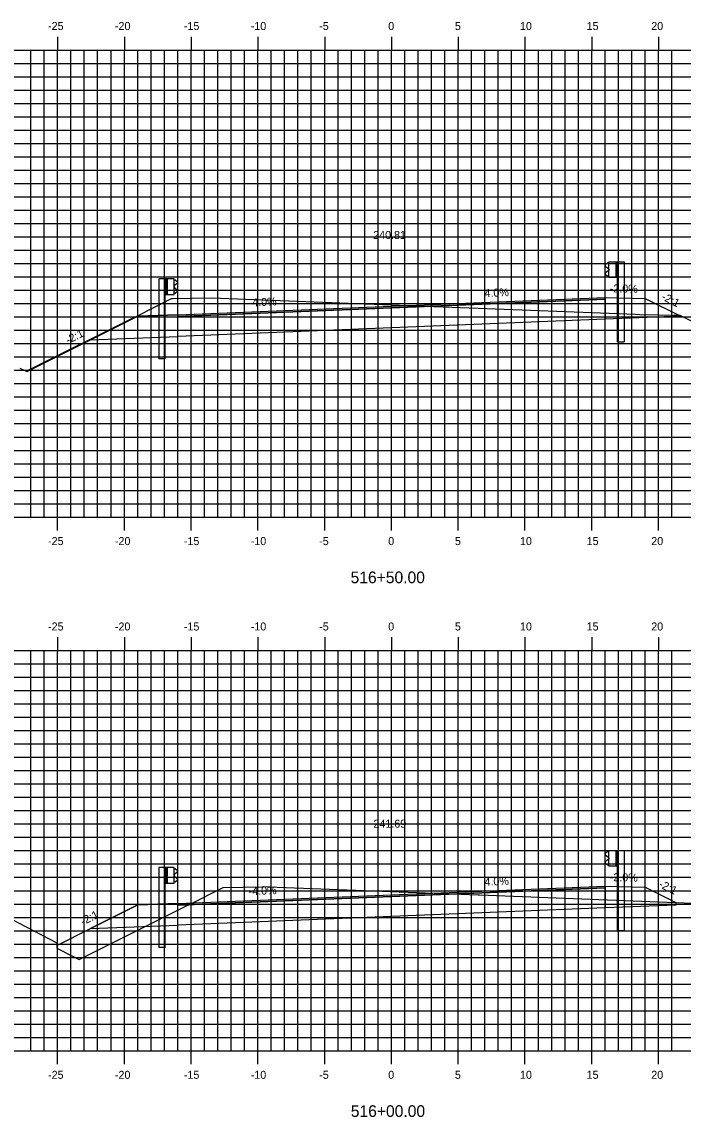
# Model space of a CAD drawing. Extents: x 1170543 to 1177585, y 609599 to 610623.
# Drawn here: x 1173703.4 to 1173752.9, y 610272.8 to 610354.9 of the extents above; entities that cross this region are included whole.
import ezdxf

# ---------------------------------------------------------------- set-up
doc = ezdxf.new("R2010")
doc.units = 0
for name, color, linetype in [('ANNOTATION', 7, 'Continuous'), ('D_Guardrail_Beam_Lt', 7, 'Continuous'), ('D_Guardrail_Beam_Rt', 7, 'Continuous'), ('D_Roadway_Centerline', 7, 'Continuous'), ('D_Roadway_Centerline_Text', 7, 'Continuous'), ('D_Roadway_Edge_Shoulder', 7, 'Continuous'), ('D_Roadway_Edge_TW', 7, 'Continuous'), ('D_Roadway_Pavement', 7, 'Continuous'), ('D_Roadway_SubGrade', 7, 'Continuous'), ('H_V ANNOTATION', 7, 'Continuous'), ('MAJOR', 7, 'Continuous'), ('MINOR', 7, 'Continuous'), ('S_Roadway_Centerline', 7, 'Continuous')]:
    doc.layers.add(name, color=color, linetype=linetype)

msp = doc.modelspace()

# ---------------------------------------------------------------- linework, layer by layer
at = {"layer": 'D_Guardrail_Beam_Lt'}
for p, q in [((1173713.634, 610335.654), (1173713.634, 610329.654)), ((1173714.104, 610335.654), (1173713.634, 610335.654)), ((1173714.792, 610335.654), (1173714.104, 610335.654)), ((1173714.104, 610335.654), (1173714.104, 610334.487)), ((1173714.167, 610335.654), (1173714.167, 610334.487)), ((1173714.271, 610335.654), (1173714.271, 610334.487)), ((1173714.792, 610334.487), (1173714.792, 610335.654)), ((1173714.792, 610335.571), (1173714.866, 610335.556)), ((1173714.882, 610335.549), (1173715.025, 610335.449)), ((1173714.866, 610334.585), (1173714.792, 610334.571)), ((1173714.796, 610335.106), (1173714.796, 610335.036)), ((1173715.025, 610335.306), (1173714.83, 610335.17)), ((1173714.83, 610334.971), (1173715.025, 610334.835)), ((1173715.025, 610334.692), (1173714.882, 610334.592)), ((1173714.104, 610334.487), (1173714.792, 610334.487)), ((1173714.125, 610329.654), (1173714.125, 610334.487)), ((1173714.125, 610329.654), (1173713.634, 610329.654)), ((1173713.634, 610291.533), (1173713.634, 610285.533)), ((1173714.104, 610291.533), (1173713.634, 610291.533)), ((1173714.792, 610291.533), (1173714.104, 610291.533)), ((1173714.104, 610291.533), (1173714.104, 610290.367)), ((1173714.167, 610291.533), (1173714.167, 610290.367)), ((1173714.271, 610291.533), (1173714.271, 610290.367)), ((1173714.792, 610290.367), (1173714.792, 610291.533)), ((1173714.792, 610291.45), (1173714.866, 610291.435)), ((1173715.025, 610291.186), (1173714.83, 610291.049)), ((1173714.882, 610291.429), (1173715.025, 610291.329)), ((1173714.104, 610290.367), (1173714.792, 610290.367)), ((1173714.125, 610285.533), (1173714.125, 610290.367)), ((1173714.866, 610290.465), (1173714.792, 610290.45)), ((1173714.796, 610290.985), (1173714.796, 610290.915)), ((1173714.83, 610290.851), (1173715.025, 610290.714)), ((1173715.025, 610290.571), (1173714.882, 610290.471)), ((1173714.125, 610285.533), (1173713.634, 610285.533))]:
    msp.add_line(p, q, dxfattribs=at)
for centre, major_axis, start_param, end_param in [((1173714.858, 610335.515), (0.0417, 0), 0.959931, 1.376053), ((1173714.975, 610335.378), (0.0877, 0), 5.323254, 7.243116), ((1173714.875, 610335.106), (-0.0789, 0), 5.323254, 6.283185), ((1173714.875, 610335.036), (-0.0789, 0), 6.283185, 7.243116), ((1173714.858, 610334.626), (0.0417, 0), 4.907132, 5.323254), ((1173714.975, 610334.764), (0.0877, 0), 5.323254, 7.243116), ((1173714.858, 610291.395), (0.0417, 0), 0.959931, 1.376053), ((1173714.975, 610291.257), (0.0877, 0), 5.323254, 7.243116), ((1173714.875, 610290.985), (-0.0789, 0), 5.323254, 6.283185), ((1173714.875, 610290.915), (-0.0789, 0), 6.283185, 7.243116), ((1173714.858, 610290.505), (0.0417, 0), 4.907132, 5.323254), ((1173714.975, 610290.643), (0.0877, 0), 5.323254, 7.243116)]:
    msp.add_ellipse(centre, major_axis=major_axis, ratio=0.995501, start_param=start_param, end_param=end_param, dxfattribs=at)
at = {"layer": 'D_Guardrail_Beam_Rt'}
for p, q in [((1173747.244, 610336.829), (1173747.1, 610336.729)), ((1173747.1, 610336.586), (1173747.296, 610336.45)), ((1173747.296, 610336.251), (1173747.1, 610336.115)), ((1173747.334, 610336.851), (1173747.26, 610336.836)), ((1173747.329, 610336.386), (1173747.329, 610336.316)), ((1173747.334, 610336.934), (1173748.021, 610336.934)), ((1173747.334, 610335.767), (1173747.334, 610336.934)), ((1173747.854, 610336.934), (1173747.854, 610335.767)), ((1173747.959, 610336.934), (1173747.959, 610335.767)), ((1173748.021, 610336.934), (1173748.492, 610336.934)), ((1173748.021, 610336.934), (1173748.021, 610335.767)), ((1173748.492, 610336.934), (1173748.492, 610330.934)), ((1173747.1, 610335.972), (1173747.244, 610335.872)), ((1173747.26, 610335.865), (1173747.334, 610335.851)), ((1173748.021, 610335.767), (1173747.334, 610335.767)), ((1173748, 610330.934), (1173748, 610335.767)), ((1173748, 610330.934), (1173748.492, 610330.934)), ((1173747.244, 610292.709), (1173747.1, 610292.609)), ((1173747.334, 610292.73), (1173747.26, 610292.715)), ((1173747.334, 610292.813), (1173748.021, 610292.813)), ((1173747.334, 610291.647), (1173747.334, 610292.813)), ((1173747.854, 610292.813), (1173747.854, 610291.647)), ((1173747.959, 610292.813), (1173747.959, 610291.647)), ((1173748.021, 610292.813), (1173748.492, 610292.813)), ((1173748.021, 610292.813), (1173748.021, 610291.647)), ((1173748.492, 610292.813), (1173748.492, 610286.813)), ((1173747.1, 610292.466), (1173747.296, 610292.329)), ((1173747.296, 610292.131), (1173747.1, 610291.994)), ((1173747.329, 610292.265), (1173747.329, 610292.195)), ((1173747.1, 610291.851), (1173747.244, 610291.751)), ((1173747.26, 610291.745), (1173747.334, 610291.73)), ((1173748.021, 610291.647), (1173747.334, 610291.647)), ((1173748, 610286.813), (1173748, 610291.647)), ((1173748, 610286.813), (1173748.492, 610286.813))]:
    msp.add_line(p, q, dxfattribs=at)
for centre, major_axis, start_param, end_param in [((1173747.151, 610336.658), (-0.0877, 0), 5.323254, 7.243116), ((1173747.268, 610336.795), (-0.0417, 0), 4.907132, 5.323254), ((1173747.25, 610336.386), (0.0789, 0), 0, 0.959931), ((1173747.25, 610336.316), (0.0789, 0), 5.323254, 6.283185), ((1173747.151, 610336.044), (-0.0877, 0), 5.323254, 7.243116), ((1173747.268, 610335.906), (-0.0417, 0), 0.959931, 1.376053), ((1173747.268, 610292.675), (-0.0417, 0), 4.907132, 5.323254), ((1173747.151, 610292.537), (-0.0877, 0), 5.323254, 7.243116), ((1173747.151, 610291.923), (-0.0877, 0), 5.323254, 7.243116), ((1173747.25, 610292.265), (0.0789, 0), 0, 0.959931), ((1173747.25, 610292.195), (0.0789, 0), 5.323254, 6.283185), ((1173747.268, 610291.785), (-0.0417, 0), 0.959931, 1.376053)]:
    msp.add_ellipse(centre, major_axis=major_axis, ratio=0.995501, start_param=start_param, end_param=end_param, dxfattribs=at)
at = {"layer": 'D_Roadway_Centerline'}
for points in [[(1173703.72, 610328.731), (1173703.774, 610328.704), (1173712.063, 610332.848), (1173715.063, 610332.968), (1173731.063, 610333.608), (1173747.063, 610334.248), (1173750.063, 610334.188), (1173752.739, 610332.85)], [(1173706, 610285.696), (1173708.53, 610286.961), (1173712.063, 610288.728), (1173715.063, 610288.848), (1173731.063, 610289.488), (1173747.063, 610290.128), (1173750.063, 610290.068), (1173752.352, 610288.923)]]:
    msp.add_lwpolyline(points, dxfattribs=at)
at = {"layer": 'D_Roadway_Edge_Shoulder'}
for points in [[(1173747.063, 610334.248), (1173747.063, 610334.123)], [(1173715.063, 610332.968), (1173715.063, 610332.843)], [(1173747.063, 610290.128), (1173747.063, 610290.003)], [(1173715.063, 610288.848), (1173715.063, 610288.723)]]:
    msp.add_lwpolyline(points, dxfattribs=at)
at = {"layer": 'D_Roadway_Edge_TW'}
for points in [[(1173715.063, 610332.843), (1173715.063, 610332.968), (1173731.063, 610333.608), (1173747.063, 610334.248), (1173747.063, 610334.123), (1173731.063, 610333.483)], [(1173715.063, 610288.723), (1173715.063, 610288.848), (1173731.063, 610289.488), (1173747.063, 610290.128), (1173747.063, 610290.003), (1173731.063, 610289.363)]]:
    msp.add_lwpolyline(points, close=True, dxfattribs=at)
at = {"layer": 'D_Roadway_Pavement'}
for points in [[(1173715.063, 610332.843), (1173715.063, 610332.843), (1173731.063, 610333.483), (1173747.063, 610334.123), (1173747.063, 610334.123), (1173731.063, 610333.483)], [(1173715.063, 610288.723), (1173715.063, 610288.723), (1173731.063, 610289.363), (1173747.063, 610290.003), (1173747.063, 610290.003), (1173731.063, 610289.363)]]:
    msp.add_lwpolyline(points, close=True, dxfattribs=at)
for points in [[(1173747.063, 610334.123), (1173747.063, 610334.123)], [(1173747.063, 610334.123), (1173747.063, 610334.123)], [(1173715.063, 610332.843), (1173715.063, 610332.843)], [(1173715.063, 610332.843), (1173715.063, 610332.843)], [(1173747.063, 610290.003), (1173747.063, 610290.003)], [(1173747.063, 610290.003), (1173747.063, 610290.003)], [(1173715.063, 610288.723), (1173715.063, 610288.723)], [(1173715.063, 610288.723), (1173715.063, 610288.723)]]:
    msp.add_lwpolyline(points, dxfattribs=at)
at = {"layer": 'D_Roadway_SubGrade'}
for points in [[(1173715.063, 610331.343), (1173715.063, 610332.843), (1173731.063, 610333.483), (1173747.063, 610334.123), (1173747.063, 610332.623), (1173731.063, 610331.983)], [(1173747.063, 610334.248), (1173750.063, 610334.188), (1173752.739, 610332.85), (1173747.063, 610332.623)], [(1173715.063, 610332.968), (1173712.063, 610332.848), (1173708.53, 610331.082), (1173715.063, 610331.343)], [(1173715.063, 610287.223), (1173715.063, 610288.723), (1173731.063, 610289.363), (1173747.063, 610290.003), (1173747.063, 610288.503), (1173731.063, 610287.863)], [(1173747.063, 610290.128), (1173750.063, 610290.068), (1173752.352, 610288.923), (1173752.352, 610288.714), (1173747.063, 610288.503)], [(1173715.063, 610288.848), (1173712.063, 610288.728), (1173708.53, 610286.961), (1173715.063, 610287.223)]]:
    msp.add_lwpolyline(points, close=True, dxfattribs=at)
at = {"layer": 'MAJOR'}
for p, q in [((1173706.063, 610353.803), (1173706.063, 610352.801)), ((1173711.063, 610353.803), (1173711.063, 610352.801)), ((1173716.063, 610353.803), (1173716.063, 610352.801)), ((1173721.063, 610353.803), (1173721.063, 610352.801)), ((1173726.063, 610353.803), (1173726.063, 610352.801)), ((1173731.063, 610353.803), (1173731.063, 610352.801)), ((1173736.063, 610353.803), (1173736.063, 610352.801)), ((1173741.063, 610353.803), (1173741.063, 610352.801)), ((1173746.063, 610353.803), (1173746.063, 610352.801)), ((1173751.063, 610353.803), (1173751.063, 610352.801)), ((1173661.063, 610352.801), (1173801.063, 610352.801)), ((1173661.063, 610352.801), (1173801.063, 610352.801)), ((1173706.063, 610317.801), (1173706.063, 610352.801)), ((1173711.063, 610317.801), (1173711.063, 610352.801)), ((1173716.063, 610317.801), (1173716.063, 610352.801)), ((1173721.063, 610317.801), (1173721.063, 610352.801)), ((1173726.063, 610317.801), (1173726.063, 610352.801)), ((1173731.063, 610317.801), (1173731.063, 610352.801)), ((1173736.063, 610317.801), (1173736.063, 610352.801)), ((1173741.063, 610317.801), (1173741.063, 610352.801)), ((1173746.063, 610317.801), (1173746.063, 610352.801)), ((1173751.063, 610317.801), (1173751.063, 610352.801)), ((1173661.063, 610347.801), (1173801.063, 610347.801)), ((1173661.063, 610342.801), (1173801.063, 610342.801)), ((1173661.063, 610337.801), (1173801.063, 610337.801)), ((1173661.063, 610332.801), (1173801.063, 610332.801)), ((1173661.063, 610327.801), (1173801.063, 610327.801)), ((1173661.063, 610322.801), (1173801.063, 610322.801)), ((1173661.063, 610317.801), (1173801.063, 610317.801)), ((1173661.063, 610317.801), (1173801.063, 610317.801)), ((1173706.063, 610316.799), (1173706.063, 610317.801)), ((1173711.063, 610316.799), (1173711.063, 610317.801)), ((1173716.063, 610316.799), (1173716.063, 610317.801)), ((1173721.063, 610316.799), (1173721.063, 610317.801)), ((1173726.063, 610316.799), (1173726.063, 610317.801)), ((1173731.063, 610316.799), (1173731.063, 610317.801)), ((1173736.063, 610316.799), (1173736.063, 610317.801)), ((1173741.063, 610316.799), (1173741.063, 610317.801)), ((1173746.063, 610316.799), (1173746.063, 610317.801)), ((1173751.063, 610316.799), (1173751.063, 610317.801)), ((1173706.063, 610308.803), (1173706.063, 610307.801)), ((1173711.063, 610308.803), (1173711.063, 610307.801)), ((1173716.063, 610308.803), (1173716.063, 610307.801)), ((1173721.063, 610308.803), (1173721.063, 610307.801)), ((1173726.063, 610308.803), (1173726.063, 610307.801)), ((1173731.063, 610308.803), (1173731.063, 610307.801)), ((1173736.063, 610308.803), (1173736.063, 610307.801)), ((1173741.063, 610308.803), (1173741.063, 610307.801)), ((1173746.063, 610308.803), (1173746.063, 610307.801)), ((1173751.063, 610308.803), (1173751.063, 610307.801)), ((1173661.063, 610307.801), (1173801.063, 610307.801)), ((1173661.063, 610307.801), (1173801.063, 610307.801)), ((1173706.063, 610277.801), (1173706.063, 610307.801)), ((1173711.063, 610277.801), (1173711.063, 610307.801)), ((1173716.063, 610277.801), (1173716.063, 610307.801)), ((1173721.063, 610277.801), (1173721.063, 610307.801)), ((1173726.063, 610277.801), (1173726.063, 610307.801)), ((1173731.063, 610277.801), (1173731.063, 610307.801)), ((1173736.063, 610277.801), (1173736.063, 610307.801)), ((1173741.063, 610277.801), (1173741.063, 610307.801)), ((1173746.063, 610277.801), (1173746.063, 610307.801)), ((1173751.063, 610277.801), (1173751.063, 610307.801)), ((1173661.063, 610302.801), (1173801.063, 610302.801)), ((1173661.063, 610297.801), (1173801.063, 610297.801)), ((1173661.063, 610292.801), (1173801.063, 610292.801)), ((1173661.063, 610287.801), (1173801.063, 610287.801)), ((1173661.063, 610282.801), (1173801.063, 610282.801)), ((1173661.063, 610277.801), (1173801.063, 610277.801)), ((1173661.063, 610277.801), (1173801.063, 610277.801)), ((1173706.063, 610276.799), (1173706.063, 610277.801)), ((1173711.063, 610276.799), (1173711.063, 610277.801)), ((1173716.063, 610276.799), (1173716.063, 610277.801)), ((1173721.063, 610276.799), (1173721.063, 610277.801)), ((1173726.063, 610276.799), (1173726.063, 610277.801)), ((1173731.063, 610276.799), (1173731.063, 610277.801)), ((1173736.063, 610276.799), (1173736.063, 610277.801)), ((1173741.063, 610276.799), (1173741.063, 610277.801)), ((1173746.063, 610276.799), (1173746.063, 610277.801)), ((1173751.063, 610276.799), (1173751.063, 610277.801))]:
    msp.add_line(p, q, dxfattribs=at)
at = {"layer": 'MINOR'}
for p, q in [((1173704.063, 610317.801), (1173704.063, 610352.801)), ((1173705.063, 610317.801), (1173705.063, 610352.801)), ((1173707.063, 610317.801), (1173707.063, 610352.801)), ((1173708.063, 610317.801), (1173708.063, 610352.801)), ((1173709.063, 610317.801), (1173709.063, 610352.801)), ((1173710.063, 610317.801), (1173710.063, 610352.801)), ((1173712.063, 610317.801), (1173712.063, 610352.801)), ((1173713.063, 610317.801), (1173713.063, 610352.801)), ((1173714.063, 610317.801), (1173714.063, 610352.801)), ((1173715.063, 610317.801), (1173715.063, 610352.801)), ((1173717.063, 610317.801), (1173717.063, 610352.801)), ((1173718.063, 610317.801), (1173718.063, 610352.801)), ((1173719.063, 610317.801), (1173719.063, 610352.801)), ((1173720.063, 610317.801), (1173720.063, 610352.801)), ((1173722.063, 610317.801), (1173722.063, 610352.801)), ((1173723.063, 610317.801), (1173723.063, 610352.801)), ((1173724.063, 610317.801), (1173724.063, 610352.801)), ((1173725.063, 610317.801), (1173725.063, 610352.801)), ((1173727.063, 610317.801), (1173727.063, 610352.801)), ((1173728.063, 610317.801), (1173728.063, 610352.801)), ((1173729.063, 610317.801), (1173729.063, 610352.801)), ((1173730.063, 610317.801), (1173730.063, 610352.801)), ((1173732.063, 610317.801), (1173732.063, 610352.801)), ((1173733.063, 610317.801), (1173733.063, 610352.801)), ((1173734.063, 610317.801), (1173734.063, 610352.801)), ((1173735.063, 610317.801), (1173735.063, 610352.801)), ((1173737.063, 610317.801), (1173737.063, 610352.801)), ((1173738.063, 610317.801), (1173738.063, 610352.801)), ((1173739.063, 610317.801), (1173739.063, 610352.801)), ((1173740.063, 610317.801), (1173740.063, 610352.801)), ((1173742.063, 610317.801), (1173742.063, 610352.801)), ((1173743.063, 610317.801), (1173743.063, 610352.801)), ((1173744.063, 610317.801), (1173744.063, 610352.801)), ((1173745.063, 610317.801), (1173745.063, 610352.801)), ((1173747.063, 610317.801), (1173747.063, 610352.801)), ((1173748.063, 610317.801), (1173748.063, 610352.801)), ((1173749.063, 610317.801), (1173749.063, 610352.801)), ((1173750.063, 610317.801), (1173750.063, 610352.801)), ((1173752.063, 610317.801), (1173752.063, 610352.801)), ((1173661.063, 610351.801), (1173801.063, 610351.801)), ((1173661.063, 610350.801), (1173801.063, 610350.801)), ((1173661.063, 610349.801), (1173801.063, 610349.801)), ((1173661.063, 610348.801), (1173801.063, 610348.801)), ((1173661.063, 610346.801), (1173801.063, 610346.801)), ((1173661.063, 610345.801), (1173801.063, 610345.801)), ((1173661.063, 610344.801), (1173801.063, 610344.801)), ((1173661.063, 610343.801), (1173801.063, 610343.801)), ((1173661.063, 610341.801), (1173801.063, 610341.801)), ((1173661.063, 610340.801), (1173801.063, 610340.801)), ((1173661.063, 610339.801), (1173801.063, 610339.801)), ((1173661.063, 610338.801), (1173801.063, 610338.801)), ((1173661.063, 610336.801), (1173801.063, 610336.801)), ((1173661.063, 610335.801), (1173801.063, 610335.801)), ((1173661.063, 610334.801), (1173801.063, 610334.801)), ((1173661.063, 610333.801), (1173801.063, 610333.801)), ((1173661.063, 610331.801), (1173801.063, 610331.801)), ((1173661.063, 610330.801), (1173801.063, 610330.801)), ((1173661.063, 610329.801), (1173801.063, 610329.801)), ((1173661.063, 610328.801), (1173801.063, 610328.801)), ((1173661.063, 610326.801), (1173801.063, 610326.801)), ((1173661.063, 610325.801), (1173801.063, 610325.801)), ((1173661.063, 610324.801), (1173801.063, 610324.801)), ((1173661.063, 610323.801), (1173801.063, 610323.801)), ((1173661.063, 610321.801), (1173801.063, 610321.801)), ((1173661.063, 610320.801), (1173801.063, 610320.801)), ((1173661.063, 610319.801), (1173801.063, 610319.801)), ((1173661.063, 610318.801), (1173801.063, 610318.801)), ((1173704.063, 610277.801), (1173704.063, 610307.801)), ((1173705.063, 610277.801), (1173705.063, 610307.801)), ((1173707.063, 610277.801), (1173707.063, 610307.801)), ((1173708.063, 610277.801), (1173708.063, 610307.801)), ((1173709.063, 610277.801), (1173709.063, 610307.801)), ((1173710.063, 610277.801), (1173710.063, 610307.801)), ((1173712.063, 610277.801), (1173712.063, 610307.801)), ((1173713.063, 610277.801), (1173713.063, 610307.801)), ((1173714.063, 610277.801), (1173714.063, 610307.801)), ((1173715.063, 610277.801), (1173715.063, 610307.801)), ((1173717.063, 610277.801), (1173717.063, 610307.801)), ((1173718.063, 610277.801), (1173718.063, 610307.801)), ((1173719.063, 610277.801), (1173719.063, 610307.801)), ((1173720.063, 610277.801), (1173720.063, 610307.801)), ((1173722.063, 610277.801), (1173722.063, 610307.801)), ((1173723.063, 610277.801), (1173723.063, 610307.801)), ((1173724.063, 610277.801), (1173724.063, 610307.801)), ((1173725.063, 610277.801), (1173725.063, 610307.801)), ((1173727.063, 610277.801), (1173727.063, 610307.801)), ((1173728.063, 610277.801), (1173728.063, 610307.801)), ((1173729.063, 610277.801), (1173729.063, 610307.801)), ((1173730.063, 610277.801), (1173730.063, 610307.801)), ((1173732.063, 610277.801), (1173732.063, 610307.801)), ((1173733.063, 610277.801), (1173733.063, 610307.801)), ((1173734.063, 610277.801), (1173734.063, 610307.801)), ((1173735.063, 610277.801), (1173735.063, 610307.801)), ((1173737.063, 610277.801), (1173737.063, 610307.801)), ((1173738.063, 610277.801), (1173738.063, 610307.801)), ((1173739.063, 610277.801), (1173739.063, 610307.801)), ((1173740.063, 610277.801), (1173740.063, 610307.801)), ((1173742.063, 610277.801), (1173742.063, 610307.801)), ((1173743.063, 610277.801), (1173743.063, 610307.801)), ((1173744.063, 610277.801), (1173744.063, 610307.801)), ((1173745.063, 610277.801), (1173745.063, 610307.801)), ((1173747.063, 610277.801), (1173747.063, 610307.801)), ((1173748.063, 610277.801), (1173748.063, 610307.801)), ((1173749.063, 610277.801), (1173749.063, 610307.801)), ((1173750.063, 610277.801), (1173750.063, 610307.801)), ((1173752.063, 610277.801), (1173752.063, 610307.801)), ((1173661.063, 610306.801), (1173801.063, 610306.801)), ((1173661.063, 610305.801), (1173801.063, 610305.801)), ((1173661.063, 610304.801), (1173801.063, 610304.801)), ((1173661.063, 610303.801), (1173801.063, 610303.801)), ((1173661.063, 610301.801), (1173801.063, 610301.801)), ((1173661.063, 610300.801), (1173801.063, 610300.801)), ((1173661.063, 610299.801), (1173801.063, 610299.801)), ((1173661.063, 610298.801), (1173801.063, 610298.801)), ((1173661.063, 610296.801), (1173801.063, 610296.801)), ((1173661.063, 610295.801), (1173801.063, 610295.801)), ((1173661.063, 610294.801), (1173801.063, 610294.801)), ((1173661.063, 610293.801), (1173801.063, 610293.801)), ((1173661.063, 610291.801), (1173801.063, 610291.801)), ((1173661.063, 610290.801), (1173801.063, 610290.801)), ((1173661.063, 610289.801), (1173801.063, 610289.801)), ((1173661.063, 610288.801), (1173801.063, 610288.801)), ((1173661.063, 610286.801), (1173801.063, 610286.801)), ((1173661.063, 610285.801), (1173801.063, 610285.801)), ((1173661.063, 610284.801), (1173801.063, 610284.801)), ((1173661.063, 610283.801), (1173801.063, 610283.801)), ((1173661.063, 610281.801), (1173801.063, 610281.801)), ((1173661.063, 610280.801), (1173801.063, 610280.801)), ((1173661.063, 610279.801), (1173801.063, 610279.801)), ((1173661.063, 610278.801), (1173801.063, 610278.801))]:
    msp.add_line(p, q, dxfattribs=at)
at = {"layer": 'S_Roadway_Centerline'}
for points in [[(1173703.247, 610328.97), (1173703.72, 610328.731), (1173711.87, 610332.807), (1173711.984, 610332.864), (1173714.598, 610334.172), (1173714.662, 610334.173), (1173717.602, 610334.234), (1173732.304, 610333.659), (1173732.305, 610333.659), (1173732.318, 610333.658), (1173733.599, 610333.609), (1173733.624, 610333.608), (1173749.333, 610332.997), (1173749.662, 610332.985), (1173752.595, 610332.929), (1173752.669, 610332.928), (1173752.76, 610332.882), (1173758.282, 610330.134)], [(1173661.063, 610297.634), (1173678.735, 610292.761), (1173688.786, 610292.393), (1173692.467, 610292.208), (1173693.249, 610292.123), (1173694.039, 610291.943), (1173694.834, 610291.667), (1173695.636, 610291.295), (1173705.997, 610285.882), (1173706.003, 610285.488), (1173707.12, 610284.92), (1173707.674, 610284.64), (1173715.716, 610288.659), (1173715.881, 610288.742), (1173718.473, 610290.037), (1173721.411, 610290.101), (1173721.484, 610290.102), (1173721.866, 610290.087), (1173734.274, 610289.614), (1173734.276, 610289.614), (1173734.282, 610289.613), (1173737.55, 610289.489), (1173737.655, 610289.485), (1173753.638, 610288.874)]]:
    msp.add_lwpolyline(points, dxfattribs=at)

# ---------------------------------------------------------------- texts
at = {"layer": 'ANNOTATION'}
for s, rotation, p in [('4.0%', 2.29061, (1173738.039, 610334.288)), ('-2.0%', 358.85424, (1173747.406, 610334.642)), ('-4.0%', 2.29061, (1173720.379, 610333.582)), ('-2:1', 333.43495, (1173751.224, 610334.126)), ('-2:1', 26.56505, (1173706.848, 610330.759)), ('-2.0%', 358.85424, (1173747.406, 610290.521)), ('4.0%', 2.29061, (1173738.039, 610290.168)), ('-2:1', 333.43495, (1173751.031, 610290.102)), ('-4.0%', 2.29061, (1173720.379, 610289.461)), ('-2:1', 26.56505, (1173707.96, 610287.194))]:
    msp.add_text(s, height=0.6, rotation=rotation, dxfattribs=at).set_placement(p)
at = {"layer": 'D_Roadway_Centerline'}
for s, p in [('C', (1173731.058, 610333.608)), ('L', (1173731.063, 610333.601)), ('C', (1173732.299, 610333.659)), ('L', (1173732.304, 610333.652)), ('C', (1173731.058, 610289.488)), ('L', (1173731.063, 610289.48))]:
    msp.add_text(s, height=0.0146, dxfattribs=at).set_placement(p)
at = {"layer": 'D_Roadway_Centerline_Text'}
for s, p in [('240.81', (1173729.693, 610338.64)), ('240.81', (1173729.693, 610338.64)), ('241.69', (1173729.714, 610294.52)), ('241.69', (1173729.714, 610294.52))]:
    msp.add_text(s, height=0.6, dxfattribs=at).set_placement(p)
at = {"layer": 'H_V ANNOTATION'}
for s, height, p in [('-25', 0.6, (1173705.348, 610354.301)), ('-20', 0.6, (1173710.356, 610354.301)), ('-15', 0.6, (1173715.52, 610354.301)), ('-10', 0.6, (1173720.528, 610354.301)), ('-5', 0.6, (1173725.653, 610354.301)), ('0', 0.6, (1173730.822, 610354.301)), ('5', 0.6, (1173735.814, 610354.301)), ('10', 0.6, (1173740.688, 610354.301)), ('15', 0.6, (1173745.68, 610354.301)), ('20', 0.6, (1173750.517, 610354.301)), ('-25', 0.6, (1173705.348, 610315.701)), ('-20', 0.6, (1173710.356, 610315.701)), ('-15', 0.6, (1173715.52, 610315.701)), ('-10', 0.6, (1173720.528, 610315.701)), ('-5', 0.6, (1173725.653, 610315.701)), ('0', 0.6, (1173730.822, 610315.701)), ('5', 0.6, (1173735.814, 610315.701)), ('10', 0.6, (1173740.688, 610315.701)), ('15', 0.6, (1173745.68, 610315.701)), ('20', 0.6, (1173750.517, 610315.701)), ('516+50.00', 0.875, (1173728.004, 610312.844)), ('-25', 0.6, (1173705.348, 610309.301)), ('-20', 0.6, (1173710.356, 610309.301)), ('-15', 0.6, (1173715.52, 610309.301)), ('-10', 0.6, (1173720.528, 610309.301)), ('-5', 0.6, (1173725.653, 610309.301)), ('0', 0.6, (1173730.822, 610309.301)), ('5', 0.6, (1173735.814, 610309.301)), ('10', 0.6, (1173740.688, 610309.301)), ('15', 0.6, (1173745.68, 610309.301)), ('20', 0.6, (1173750.517, 610309.301)), ('-25', 0.6, (1173705.348, 610275.701)), ('-20', 0.6, (1173710.356, 610275.701)), ('-15', 0.6, (1173715.52, 610275.701)), ('-10', 0.6, (1173720.528, 610275.701)), ('-5', 0.6, (1173725.653, 610275.701)), ('0', 0.6, (1173730.822, 610275.701)), ('5', 0.6, (1173735.814, 610275.701)), ('10', 0.6, (1173740.688, 610275.701)), ('15', 0.6, (1173745.68, 610275.701)), ('20', 0.6, (1173750.517, 610275.701)), ('516+00.00', 0.875, (1173728.02, 610272.844))]:
    msp.add_text(s, height=height, dxfattribs=at).set_placement(p)

doc.saveas('drawing.dxf')
